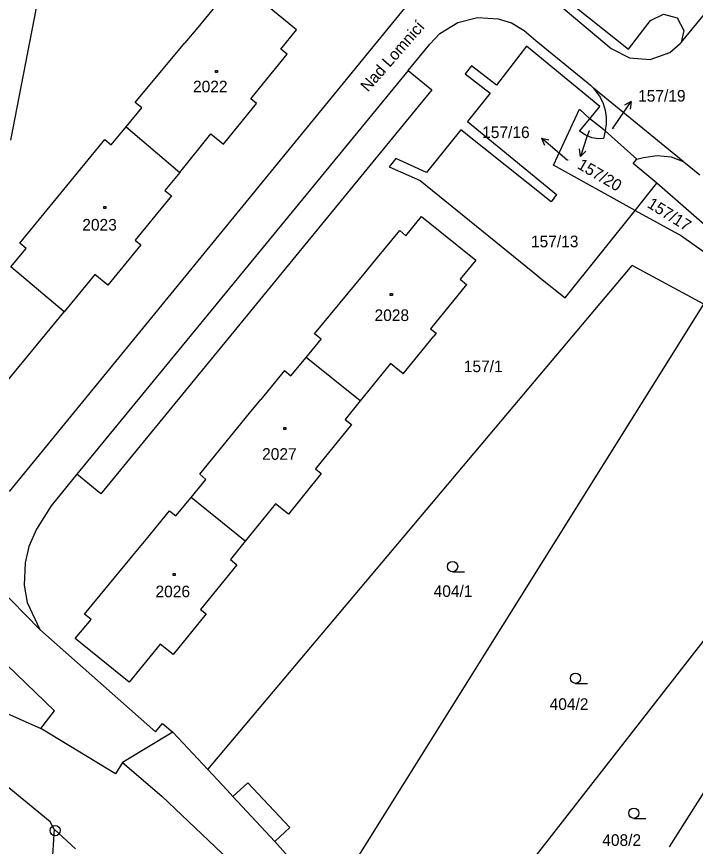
# Model space of a CAD drawing. Extents: x -795483 to -789093, y -1112258 to -1108741.
# Drawn here: x -791422.1 to -791322.7, y -1110899.6 to -1110778 of the extents above; entities that cross this region are included whole.
import ezdxf

# ---------------------------------------------------------------- set-up
doc = ezdxf.new("R2010")
doc.units = 0
for name, color, linetype in [('Komunikace', 7, 'Continuous'), ('Vrstva 1', 7, 'Continuous'), ('Vrstva 14', 7, 'Continuous'), ('Vrstva 15', 7, 'Continuous'), ('Vrstva 16', 7, 'Continuous'), ('Vrstva 2', 7, 'Continuous'), ('Vrstva 23', 7, 'Continuous'), ('Vrstva 25', 7, 'Continuous'), ('Vrstva 28', 7, 'Continuous'), ('Vrstva 38', 7, 'Continuous')]:
    doc.layers.add(name, color=color, linetype=linetype)

msp = doc.modelspace()

# ---------------------------------------------------------------- linework, layer by layer
at = {"layer": 'Komunikace'}
for p, q in [((-791334.86, -1110794.44), (-791333.82, -1110792.94)), ((-791338.3, -1110794.76), (-791338.6, -1110795.65)), ((-791341.45, -1110799.09), (-791342.98, -1110797.77))]:
    msp.add_line(p, q, dxfattribs=at)
at = {"layer": 'Vrstva 1'}
for p, q in [((-791417.16, -1110765.64), (-791423.03, -1110796.12)), ((-791347.32, -1110772.33), (-791335.06, -1110782.68)), ((-791342.82, -1110774.58), (-791332.54, -1110782.8)), ((-791392.22, -1110775.48), (-791395.61, -1110779.59)), ((-791423.19, -1110847.57), (-791365.28, -1110776.78)), ((-791381.16, -1110779.96), (-791384.92, -1110776.88)), ((-791324.82, -1110781.81), (-791320.21, -1110776.23)), ((-791357.51, -1110778.87), (-791354.61, -1110778.13)), ((-791354.61, -1110778.13), (-791351.59, -1110778.32)), ((-791329.28, -1110778.58), (-791327.4, -1110777.65)), ((-791327.4, -1110777.65), (-791325.4, -1110778.22)), ((-791325.4, -1110778.22), (-791324.41, -1110780.05)), ((-791360.16, -1110780.48), (-791357.51, -1110778.87)), ((-791351.59, -1110778.32), (-791349.65, -1110778.95)), ((-791349.65, -1110778.95), (-791347.8, -1110780.06)), ((-791332.54, -1110782.8), (-791329.28, -1110778.58)), ((-791395.61, -1110779.59), (-791397.5, -1110781.88)), ((-791383.43, -1110782.77), (-791381.16, -1110779.96)), ((-791361.63, -1110782.04), (-791360.16, -1110780.48)), ((-791347.8, -1110780.06), (-791346.1, -1110781.5)), ((-791324.41, -1110780.05), (-791324.82, -1110781.81)), ((-791404.75, -1110790.59), (-791397.5, -1110781.88)), ((-791346.1, -1110781.5), (-791340, -1110786.49)), ((-791324.96, -1110781.98), (-791324.82, -1110781.81)), ((-791382.51, -1110783.51), (-791383.43, -1110782.77)), ((-791364.8, -1110785.93), (-791361.63, -1110782.04)), ((-791347.47, -1110782.36), (-791351.83, -1110788.07)), ((-791336.73, -1110791.19), (-791347.47, -1110782.36)), ((-791335.06, -1110782.68), (-791332.39, -1110784.07)), ((-791326.48, -1110783.26), (-791324.96, -1110781.98)), ((-791387.82, -1110790.06), (-791382.51, -1110783.51)), ((-791332.39, -1110784.07), (-791329.35, -1110784.31)), ((-791329.35, -1110784.31), (-791326.48, -1110783.26)), ((-791355.49, -1110785.24), (-791356.45, -1110786.42)), ((-791351.83, -1110788.07), (-791355.49, -1110785.24)), ((-791364.8, -1110785.93), (-791361.34, -1110788.75)), ((-791356.45, -1110786.42), (-791352.79, -1110789.25)), ((-791340, -1110786.49), (-791338.42, -1110787.78)), ((-791338.42, -1110787.78), (-791338.09, -1110788.08)), ((-791361.34, -1110788.75), (-791409.81, -1110847.91)), ((-791338.09, -1110788.08), (-791337.65, -1110788.48)), ((-791337.65, -1110788.48), (-791336.67, -1110789.83)), ((-791324.5, -1110799.24), (-791337.65, -1110788.48)), ((-791386.98, -1110790.74), (-791387.82, -1110790.06)), ((-791352.79, -1110789.25), (-791356.12, -1110793.4)), ((-791336.67, -1110789.83), (-791336.24, -1110790.76)), ((-791406.1, -1110794.15), (-791403.81, -1110791.38)), ((-791403.81, -1110791.38), (-791404.75, -1110790.59)), ((-791389.08, -1110793.33), (-791386.98, -1110790.74)), ((-791343.49, -1110799.78), (-791339.68, -1110791.57)), ((-791339.68, -1110791.57), (-791338.2, -1110792.98)), ((-791338.2, -1110792.98), (-791336.73, -1110791.19)), ((-791336.24, -1110790.76), (-791335.94, -1110791.74)), ((-791335.94, -1110791.74), (-791335.78, -1110792.74)), ((-791335.78, -1110792.74), (-791335.78, -1110793.75)), ((-791391.83, -1110796.72), (-791389.08, -1110793.33)), ((-791356.12, -1110793.4), (-791343.05, -1110804.06)), ((-791339.7, -1110794.8), (-791338.2, -1110792.98)), ((-791335.91, -1110794.75), (-791338.2, -1110792.98)), ((-791335.78, -1110793.75), (-791335.91, -1110794.75)), ((-791408.28, -1110796.81), (-791406.1, -1110794.15)), ((-791406.1, -1110794.15), (-791398.24, -1110800.84)), ((-791398.24, -1110800.84), (-791393.68, -1110795.2)), ((-791393.68, -1110795.2), (-791391.83, -1110796.72)), ((-791357.05, -1110794.58), (-791362.08, -1110800.85)), ((-791343.86, -1110805.14), (-791357.05, -1110794.58)), ((-791338.86, -1110795.34), (-791339.7, -1110794.8)), ((-791335.91, -1110794.75), (-791336.18, -1110795.88)), ((-791331.3, -1110798.89), (-791335.91, -1110794.75)), ((-791421.68, -1110811.2), (-791409.22, -1110796.04)), ((-791409.22, -1110796.04), (-791408.28, -1110796.81)), ((-791337.91, -1110795.76), (-791338.86, -1110795.34)), ((-791336.9, -1110795.92), (-791337.91, -1110795.76)), ((-791336.18, -1110795.88), (-791336.9, -1110795.92)), ((-791366.59, -1110798.8), (-791367.59, -1110800.03)), ((-791362.08, -1110800.85), (-791366.59, -1110798.8)), ((-791331.81, -1110799.55), (-791331.3, -1110798.89)), ((-791331.3, -1110798.89), (-791330.3, -1110798.66)), ((-791330.3, -1110798.66), (-791328.32, -1110798.38)), ((-791328.32, -1110798.38), (-791326.29, -1110798.58)), ((-791326.29, -1110798.58), (-791324.5, -1110799.24)), ((-791367.59, -1110800.03), (-791363.05, -1110802.02)), ((-791331.56, -1110806.43), (-791343.49, -1110799.78)), ((-791328.35, -1110802.43), (-791331.81, -1110799.55)), ((-791324.5, -1110799.24), (-791324.4, -1110799.28)), ((-791324.4, -1110799.28), (-791323.61, -1110799.93)), ((-791323.61, -1110799.93), (-791322.07, -1110801.19)), ((-791398.24, -1110800.84), (-791400.43, -1110803.49)), ((-791363.05, -1110802.02), (-791346.53, -1110815.4)), ((-791331.56, -1110806.43), (-791328.35, -1110802.43)), ((-791290.8, -1110835.27), (-791328.35, -1110802.43)), ((-791400.43, -1110803.49), (-791399.46, -1110804.28)), ((-791399.46, -1110804.28), (-791404.78, -1110810.75)), ((-791343.05, -1110804.06), (-791343.86, -1110805.14)), ((-791365.11, -1110810.11), (-791362.82, -1110807.32)), ((-791362.82, -1110807.32), (-791354.86, -1110813.7)), ((-791341.81, -1110819.21), (-791331.56, -1110806.43)), ((-791331.56, -1110806.43), (-791324.76, -1110810.12)), ((-791369.52, -1110813.59), (-791365.99, -1110809.35)), ((-791365.99, -1110809.35), (-791365.11, -1110810.11)), ((-791404.78, -1110810.75), (-791403.93, -1110811.45)), ((-791324.76, -1110810.12), (-791318.47, -1110814.59)), ((-791422.97, -1110814.69), (-791420.74, -1110811.98)), ((-791420.74, -1110811.98), (-791421.68, -1110811.2)), ((-791403.93, -1110811.45), (-791408.77, -1110817.34)), ((-791415.16, -1110821.26), (-791422.97, -1110814.69)), ((-791394.14, -1110888.32), (-791332, -1110814.5)), ((-791371.23, -1110815.68), (-791369.52, -1110813.59)), ((-791354.86, -1110813.7), (-791357.16, -1110816.49)), ((-791321.48, -1110820.16), (-791332, -1110814.5)), ((-791410.66, -1110815.79), (-791415.16, -1110821.26)), ((-791408.77, -1110817.34), (-791410.66, -1110815.79)), ((-791378.49, -1110824.48), (-791371.23, -1110815.68)), ((-791346.53, -1110815.4), (-791345.34, -1110816.36)), ((-791357.16, -1110816.49), (-791356.24, -1110817.24)), ((-791345.34, -1110816.36), (-791341.81, -1110819.21)), ((-791356.24, -1110817.24), (-791361.52, -1110823.75)), ((-791376.33, -1110907.78), (-791321.48, -1110820.16)), ((-791424.49, -1110832.59), (-791415.16, -1110821.26)), ((-791361.52, -1110823.75), (-791360.7, -1110824.41)), ((-791360.7, -1110824.41), (-791361.05, -1110824.84)), ((-791379.74, -1110827.94), (-791377.55, -1110825.28)), ((-791377.55, -1110825.28), (-791378.49, -1110824.48)), ((-791365.51, -1110830.35), (-791361.05, -1110824.84)), ((-791381.95, -1110830.64), (-791379.74, -1110827.94)), ((-791371.81, -1110834.3), (-791379.74, -1110827.94)), ((-791367.38, -1110828.83), (-791371.81, -1110834.3)), ((-791365.51, -1110830.35), (-791367.38, -1110828.83)), ((-791382.88, -1110829.88), (-791386.36, -1110834.12)), ((-791382.88, -1110829.88), (-791381.95, -1110830.64)), ((-791388.01, -1110836.13), (-791386.36, -1110834.12)), ((-791371.81, -1110834.3), (-791374.01, -1110837.02)), ((-791395.32, -1110845.05), (-791388.01, -1110836.13)), ((-791373.1, -1110837.76), (-791378.38, -1110844.28)), ((-791374.01, -1110837.02), (-791373.1, -1110837.76)), ((-791413.3, -1110845.04), (-791417.09, -1110849.68)), ((-791409.81, -1110847.91), (-791413.3, -1110845.04)), ((-791394.4, -1110845.81), (-791395.32, -1110845.05)), ((-791377.52, -1110844.97), (-791382.33, -1110850.9)), ((-791378.38, -1110844.28), (-791377.52, -1110844.97)), ((-791439.95, -1110846.26), (-791418.75, -1110867.78)), ((-791396.58, -1110848.47), (-791394.4, -1110845.81)), ((-791398.8, -1110851.17), (-791396.58, -1110848.47)), ((-791388.66, -1110854.87), (-791396.58, -1110848.47)), ((-791417.09, -1110849.68), (-791419.24, -1110853.1)), ((-791384.21, -1110849.38), (-791388.66, -1110854.87)), ((-791382.33, -1110850.9), (-791384.21, -1110849.38)), ((-791403.17, -1110854.62), (-791399.72, -1110850.41)), ((-791399.72, -1110850.41), (-791398.8, -1110851.17)), ((-791419.24, -1110853.1), (-791420.37, -1110855.65)), ((-791404.85, -1110856.66), (-791403.17, -1110854.62)), ((-791420.37, -1110855.65), (-791420.89, -1110858.03)), ((-791388.66, -1110854.87), (-791390.83, -1110857.55)), ((-791412.17, -1110865.57), (-791404.85, -1110856.66)), ((-791420.89, -1110858.03), (-791421.01, -1110861.32)), ((-791389.89, -1110858.32), (-791395.19, -1110864.85)), ((-791390.83, -1110857.55), (-791389.89, -1110858.32)), ((-791421.01, -1110861.32), (-791420.59, -1110863.84)), ((-791420.59, -1110863.84), (-791418.75, -1110867.78)), ((-791411.24, -1110866.33), (-791412.17, -1110865.57)), ((-791394.38, -1110865.52), (-791399.2, -1110871.47)), ((-791395.19, -1110864.85), (-791394.38, -1110865.52)), ((-791413.55, -1110869.12), (-791411.24, -1110866.33)), ((-791418.75, -1110867.78), (-791401.77, -1110882.8)), ((-791368.77, -1110929.98), (-791320.01, -1110867.55)), ((-791416.58, -1110879.71), (-791428.26, -1110868.46)), ((-791405.64, -1110875.54), (-791413.55, -1110869.12)), ((-791401.09, -1110869.93), (-791405.64, -1110875.54)), ((-791399.2, -1110871.47), (-791401.09, -1110869.93)), ((-791432.7, -1110875.99), (-791418.58, -1110882.32)), ((-791417.23, -1110896), (-791437.03, -1110879.71)), ((-791418.58, -1110882.32), (-791416.58, -1110879.71)), ((-791407.66, -1110888.97), (-791418.58, -1110882.32)), ((-791401.77, -1110882.8), (-791400.76, -1110881.59)), ((-791400.76, -1110881.59), (-791399.26, -1110882.84)), ((-791399.26, -1110882.84), (-791406.61, -1110887.29)), ((-791399.26, -1110882.84), (-791394.14, -1110888.32)), ((-791316.51, -1110883.74), (-791326.58, -1110899.63)), ((-791406.61, -1110887.29), (-791407.66, -1110888.97)), ((-791406.61, -1110887.29), (-791400.89, -1110892.21)), ((-791391.31, -1110891.36), (-791394.14, -1110888.32)), ((-791400.89, -1110892.21), (-791389.2, -1110903.27)), ((-791391.31, -1110891.36), (-791390.45, -1110892.29)), ((-791384.32, -1110898.86), (-791390.45, -1110892.29)), ((-791416.64, -1110897.04), (-791417.23, -1110896)), ((-791416.64, -1110897.04), (-791417.72, -1110914.18)), ((-791413.51, -1110899.93), (-791416.64, -1110897.04)), ((-791376.33, -1110907.78), (-791384.32, -1110898.86))]:
    msp.add_line(p, q, dxfattribs=at)
at = {"layer": 'Vrstva 16'}
for p, q in [((-791333.82, -1110792.94), (-791332.11, -1110790.47)), ((-791332.11, -1110790.47), (-791333.09, -1110791.01)), ((-791332.11, -1110790.47), (-791332.27, -1110791.58)), ((-791342.98, -1110797.77), (-791345.25, -1110795.81)), ((-791345.25, -1110795.81), (-791344.82, -1110796.84)), ((-791345.25, -1110795.81), (-791344.17, -1110796.08)), ((-791338.6, -1110795.65), (-791339.55, -1110798.5)), ((-791339.55, -1110798.5), (-791339.71, -1110797.39)), ((-791339.55, -1110798.5), (-791338.76, -1110797.71))]:
    msp.add_line(p, q, dxfattribs=at)
at = {"layer": 'Vrstva 2'}
for p, q in [((-791364.8, -1110785.93), (-791413.3, -1110845.04)), ((-791390.45, -1110892.29), (-791388.25, -1110890.24)), ((-791388.25, -1110890.24), (-791382.1, -1110896.79)), ((-791382.1, -1110896.79), (-791384.32, -1110898.86))]:
    msp.add_line(p, q, dxfattribs=at)
at = {"layer": 'Vrstva 23'}
for p, q in [((-791358.28, -1110859.34), (-791356.53, -1110859.34)), ((-791340.28, -1110875.69), (-791338.53, -1110875.69)), ((-791331.74, -1110895.47), (-791329.99, -1110895.47))]:
    msp.add_line(p, q, dxfattribs=at)
for centre in [(-791358.28, -1110858.59), (-791340.28, -1110874.94), (-791331.74, -1110894.72)]:
    msp.add_circle(centre, 0.75, dxfattribs=at)
at = {"layer": 'Vrstva 25'}
for p, q in [((-791392.99, -1110785.91), (-791392.69, -1110785.91)), ((-791392.99, -1110786.21), (-791392.99, -1110785.91)), ((-791392.69, -1110786.21), (-791392.99, -1110786.21)), ((-791392.69, -1110785.91), (-791392.69, -1110786.21)), ((-791409.38, -1110805.82), (-791409.08, -1110805.82)), ((-791409.38, -1110806.12), (-791409.38, -1110805.82)), ((-791409.08, -1110806.12), (-791409.38, -1110806.12)), ((-791409.08, -1110805.82), (-791409.08, -1110806.12)), ((-791367.4, -1110818.56), (-791367.1, -1110818.56)), ((-791367.4, -1110818.86), (-791367.4, -1110818.56)), ((-791367.1, -1110818.86), (-791367.4, -1110818.86)), ((-791367.1, -1110818.56), (-791367.1, -1110818.86)), ((-791383.01, -1110838.22), (-791382.71, -1110838.22)), ((-791383.01, -1110838.52), (-791383.01, -1110838.22)), ((-791382.71, -1110838.52), (-791383.01, -1110838.52)), ((-791382.71, -1110838.22), (-791382.71, -1110838.52)), ((-791399.19, -1110859.61), (-791398.89, -1110859.61)), ((-791399.19, -1110859.91), (-791399.19, -1110859.61)), ((-791398.89, -1110859.61), (-791398.89, -1110859.91)), ((-791398.89, -1110859.91), (-791399.19, -1110859.91))]:
    msp.add_line(p, q, dxfattribs=at)
at = {"layer": 'Vrstva 28'}
for radius in [0.75, 0.01]:
    msp.add_circle((-791416.49, -1110897.27), radius, dxfattribs=at)

# ---------------------------------------------------------------- texts
at = {"layer": 'Vrstva 14'}
for s, height, p in [('157/20', 0.1, (-791338.3, -1110794.76)), ('157/19', 0.1, (-791334.86, -1110794.44)), ('157/16', 0.1, (-791341.45, -1110799.09)), ('157/13', 1.7, (-791346.8, -1110811.8)), ('157/1', 1.7, (-791356.64, -1110830.1)), ('404/1', 1.7, (-791361.06, -1110863.03)), ('404/2', 1.7, (-791344.07, -1110879.58)), ('408/2', 1.7, (-791336.36, -1110899.5))]:
    msp.add_text(s, height=height, dxfattribs=at).set_placement(p)
msp.add_text('157/17', height=1.7, rotation=327.8281, dxfattribs=at).set_placement((-791329.91, -1110805.85))
at = {"layer": 'Vrstva 15'}
for s, p in [('2022', (-791396.3, -1110789.11)), ('2023', (-791412.52, -1110809.36)), ('2028', (-791369.71, -1110822.61)), ('2027', (-791386.18, -1110842.94)), ('2026', (-791401.79, -1110863.08))]:
    msp.add_text(s, height=1.7, dxfattribs=at).set_placement(p)
at = {"layer": 'Vrstva 16'}
for s, p in [('157/19', (-791331.11, -1110790.47)), ('157/16', (-791353.95, -1110795.81))]:
    msp.add_text(s, height=1.7, dxfattribs=at).set_placement(p)
msp.add_text('157/20', height=1.7, rotation=329.4655, dxfattribs=at).set_placement((-791340.15, -1110800.16))
at = {"layer": 'Vrstva 38'}
msp.add_text('Nad Lomnicí', height=1.7, rotation=48.7266, dxfattribs=at).set_placement((-791370.67, -1110789.16))

doc.saveas('drawing.dxf')
